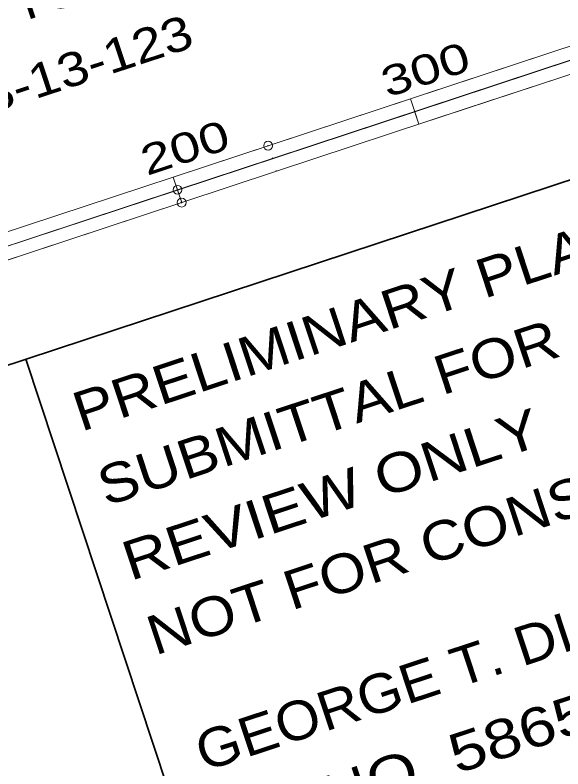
# Model space of a CAD drawing. Extents: x 2355803 to 2371254, y 6970215 to 6985302.
# Drawn here: x 2357244.6 to 2357464, y 6973840.5 to 6974142.6 of the extents above; entities that cross this region are included whole.
import ezdxf

# ---------------------------------------------------------------- set-up
doc = ezdxf.new("R2010")
doc.units = 0
doc.header["$LTSCALE"] = 7.1
doc.header["$PDMODE"] = 32
doc.header["$PDSIZE"] = 3.55
doc.layers.add('19', color=7, linetype='Continuous', lineweight=13)
doc.layers.add('8', color=7, linetype='Continuous', lineweight=13)

msp = doc.modelspace()

# ---------------------------------------------------------------- linework, layer by layer
at = {"layer": '19', "lineweight": 35}
for p, q in [((2357566.598, 6974109.603), (2356800.078, 6973856.379)), ((2357338.07, 6973734.835), (2357248.932, 6974004.659))]:
    msp.add_line(p, q, dxfattribs=at)
at = {"layer": '19'}
for p, q in [((2357118.063, 6974014.995), (2357307.971, 6974077.733)), ((2357232.008, 6974052.637), (2357307.971, 6974077.733)), ((2357309.663, 6974072.611), (2357307.971, 6974077.733)), ((2357309.664, 6974072.611), (2357307.971, 6974077.732)), ((2357309.396, 6974072.522), (2357309.751, 6974072.343)), ((2357309.485, 6974072.552), (2357309.721, 6974072.433)), ((2357309.575, 6974072.582), (2357309.691, 6974072.522)), ((2357311.355, 6974067.489), (2357309.664, 6974072.611)), ((2357309.689, 6974072.533), (2357309.742, 6974072.636)), ((2357309.72, 6974072.443), (2357309.831, 6974072.666)), ((2357311.355, 6974067.489), (2357235.391, 6974042.394)), ((2357311.062, 6974067.392), (2357311.258, 6974067.781)), ((2357311.152, 6974067.423), (2357311.287, 6974067.691)), ((2357311.241, 6974067.452), (2357311.316, 6974067.602)), ((2357311.276, 6974067.729), (2357311.595, 6974067.568)), ((2357311.306, 6974067.639), (2357311.505, 6974067.539)), ((2357311.331, 6974067.482), (2357311.347, 6974067.513))]:
    msp.add_line(p, q, dxfattribs=at)
msp.add_lwpolyline([(2357214.764, 6974041.139), (2357309.699, 6974072.501), (2357311.355, 6974067.489), (2357216.419, 6974036.127)], close=True, dxfattribs=at)
msp.add_lwpolyline([(2357233.699, 6974047.516), (2357309.663, 6974072.611), (2357311.355, 6974067.489)], dxfattribs=at)
for p in [(2357309.664, 6974072.611), (2357311.355, 6974067.489)]:
    msp.add_point(p, dxfattribs=at)
at = {"layer": '8'}
for p, q in [((2357307.971, 6974077.732), (2357497.879, 6974140.47)), ((2357421.916, 6974115.374), (2357497.879, 6974140.47)), ((2357501.263, 6974130.226), (2357425.299, 6974105.131)), ((2357345.953, 6974090.28), (2357421.916, 6974115.374)), ((2357421.874, 6974115.36), (2357421.93, 6974115.332)), ((2357423.607, 6974110.253), (2357347.645, 6974085.158)), ((2357402.925, 6974109.101), (2357406.309, 6974098.858)), ((2357349.337, 6974080.037), (2357425.299, 6974105.131)), ((2357307.971, 6974077.732), (2357345.953, 6974090.28)), ((2357345.982, 6974090.194), (2357346.039, 6974090.308)), ((2357346.011, 6974090.105), (2357346.128, 6974090.337)), ((2357309.664, 6974072.611), (2357347.645, 6974085.158)), ((2357347.485, 6974085.105), (2357347.699, 6974084.998)), ((2357347.573, 6974085.135), (2357347.668, 6974085.087)), ((2357347.578, 6974085.361), (2357347.848, 6974085.225)), ((2357347.607, 6974085.272), (2357347.758, 6974085.196)), ((2357347.637, 6974085.183), (2357347.669, 6974085.166)), ((2357349.015, 6974079.93), (2357349.231, 6974080.359)), ((2357118.063, 6974014.995), (2357307.971, 6974077.733)), ((2357232.008, 6974052.637), (2357307.971, 6974077.733)), ((2357309.663, 6974072.611), (2357307.971, 6974077.733)), ((2357309.664, 6974072.611), (2357307.971, 6974077.732)), ((2357349.104, 6974079.96), (2357349.26, 6974080.269)), ((2357309.396, 6974072.522), (2357309.751, 6974072.343)), ((2357309.485, 6974072.552), (2357309.721, 6974072.433)), ((2357309.575, 6974072.582), (2357309.691, 6974072.522)), ((2357309.689, 6974072.533), (2357309.742, 6974072.636)), ((2357309.72, 6974072.443), (2357309.831, 6974072.666)), ((2357311.355, 6974067.489), (2357235.391, 6974042.394)), ((2357311.062, 6974067.392), (2357311.258, 6974067.781)), ((2357311.152, 6974067.423), (2357311.287, 6974067.691)), ((2357311.241, 6974067.452), (2357311.316, 6974067.602)), ((2357311.276, 6974067.729), (2357311.595, 6974067.568)), ((2357311.306, 6974067.639), (2357311.505, 6974067.539)), ((2357311.331, 6974067.482), (2357311.347, 6974067.513))]:
    msp.add_line(p, q, dxfattribs=at)
at = {"layer": '8', "lineweight": 35}
for p, q in [((2357566.598, 6974109.603), (2356800.078, 6973856.379)), ((2357338.07, 6973734.835), (2357248.932, 6974004.659))]:
    msp.add_line(p, q, dxfattribs=at)
at = {"layer": '8'}
for points in [[(2357404.672, 6974103.876), (2357499.607, 6974135.238), (2357501.263, 6974130.226), (2357406.327, 6974098.864)], [(2357307.971, 6974077.732), (2357402.944, 6974109.107), (2357404.672, 6974103.876), (2357309.699, 6974072.502)], [(2357214.764, 6974041.139), (2357309.699, 6974072.501), (2357311.355, 6974067.489), (2357216.419, 6974036.127)]]:
    msp.add_lwpolyline(points, close=True, dxfattribs=at)
for points in [[(2357423.607, 6974110.253), (2357499.571, 6974135.348), (2357501.263, 6974130.226)], [(2357349.337, 6974080.037), (2357311.355, 6974067.489), (2357309.664, 6974072.611)], [(2357233.699, 6974047.516), (2357309.663, 6974072.611), (2357311.355, 6974067.489)]]:
    msp.add_lwpolyline(points, dxfattribs=at)
for p in [(2357345.953, 6974090.28), (2357309.664, 6974072.611), (2357311.355, 6974067.489)]:
    msp.add_point(p, dxfattribs=at)

# ---------------------------------------------------------------- texts
at = {"layer": '19'}
for s, height, width, p in [(' HOV ALTERNATIVE 5A', 23.33, 1.6, (2356847.786, 6974066.579)), ('LIMITS:  NORTH INTERCHANGE SH 121 TO RANDOL MILL ROAD', 13.58, 1.15, (2356867.926, 6974014.529)), ('CONTROL NO.  0008-13-123', 13.58, 1.2, (2357044.55, 6974040.119)), ('200', 12, 1.35, (2357297.385, 6974078.156)), ('PRELIMINARY PLAN', 15.66, 1.15, (2357271.076, 6973975.577)), ('SUBMITTAL FOR', 15.66, 1.15, (2357280.954, 6973945.677)), ('NOT FOR CONSTRUCTION.', 15.66, 1.15, (2357300.708, 6973885.883)), ('REVIEW ONLY', 15.66, 1.2, (2357290.83, 6973915.783)), ('GEORGE T. DIAMOND', 15.65, 1.1, (2357320.134, 6973839.319)), ('PE NO. 58650', 15.65, 1.25, (2357330.374, 6973808.327))]:
    msp.add_text(s, height=height, rotation=18.281, dxfattribs=dict(at, width=width)).set_placement(p)
at = {"layer": '8'}
for s, height, width, p in [(' HOV ALTERNATIVE 5A', 23.33, 1.6, (2356847.786, 6974066.579)), ('LIMITS:  NORTH INTERCHANGE SH 121 TO RANDOL MILL ROAD', 13.58, 1.15, (2356867.926, 6974014.529)), ('CONTROL NO.  0008-13-123', 13.58, 1.2, (2357044.55, 6974040.119)), ('300', 12, 1.35, (2357393.655, 6974109.484)), ('200', 12, 1.35, (2357297.385, 6974078.156)), ('PRELIMINARY PLAN', 15.66, 1.15, (2357271.076, 6973975.577)), ('SUBMITTAL FOR', 15.66, 1.15, (2357280.954, 6973945.677)), ('NOT FOR CONSTRUCTION.', 15.66, 1.15, (2357300.708, 6973885.883)), ('REVIEW ONLY', 15.66, 1.2, (2357290.83, 6973915.783)), ('GEORGE T. DIAMOND', 15.65, 1.1, (2357320.134, 6973839.319)), ('PE NO. 58650', 15.65, 1.25, (2357330.374, 6973808.327))]:
    msp.add_text(s, height=height, rotation=18.281, dxfattribs=dict(at, width=width)).set_placement(p)

doc.saveas('drawing.dxf')
